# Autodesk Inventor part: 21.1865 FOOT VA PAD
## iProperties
Created: 2007-11
Part Number: 21.1865 FOOT VA PAD
Material: Stainless Steel
Document SubType Name: Modeling
Designer: Andy Moles
Density: 8.08 g/cm^3
Mass: 134.456 g
Surface Area: 57.4594 cm^2
Volume: 16.6406 cm^3
Author: Andy Moles
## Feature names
1. Base1
2. Extrusion1
3. Extrusion2
4. Extrusion3
